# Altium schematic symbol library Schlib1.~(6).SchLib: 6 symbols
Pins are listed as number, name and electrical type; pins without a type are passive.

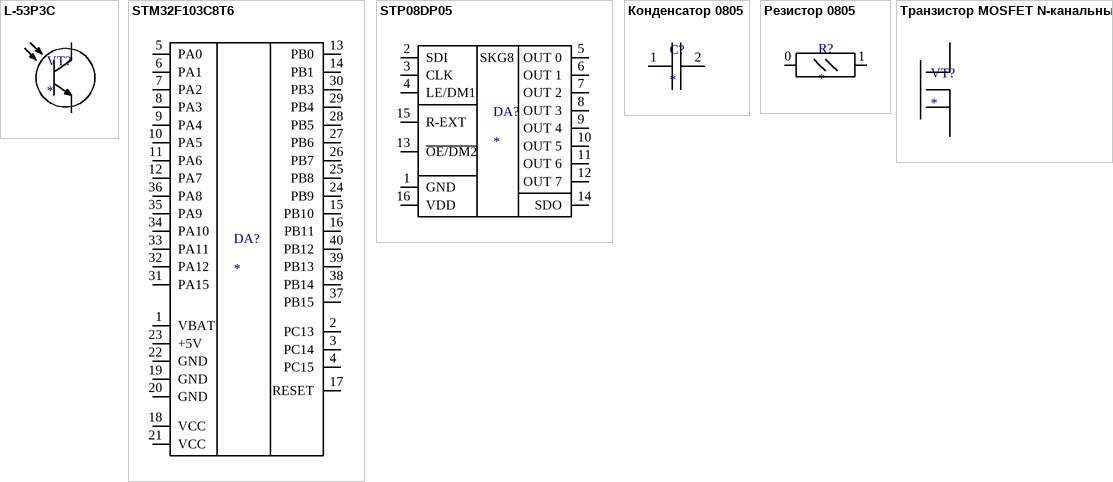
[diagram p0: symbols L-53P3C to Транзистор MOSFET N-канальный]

## L-53P3C
designator VT?

## STM32F103C8T6
designator DA?
pins: 1 VBAT, 2 PC13, 3 PC14, 4 PC15, 5 PA0, 6 PA1, 7 PA2, 8 PA3, 9 PA4, 10 PA5, 11 PA6, 12 PA7, 13 PB0, 14 PB1, 15 PB10, 16 PB11, 17 RESET, 18 VCC, 19 GND, 20 GND, 21 VCC, 22 GND, 23 +5V, 24 PB9, 25 PB8, 26 PB7, 27 PB6, 28 PB5, 29 PB4, 30 PB3, 31 PA15, 32 PA12, 33 PA11, 34 PA10, 35 PA9, 36 PA8, 37 PB15, 38 PB14, 39 PB13, 40 PB12

## STP08DP05
designator DA?
pins: 1 GND, 2 SDI, 3 CLK, 4 LE/DM1, 5 OUT 0, 6 OUT 1, 7 OUT 2, 8 OUT 3, 9 OUT 4, 10 OUT 5, 11 OUT 6, 12 OUT 7, 13 ~{OE/DM2}, 14 SDO, 15 R-EXT, 16 VDD

## Конденсатор 0805
designator С?
pins: 1, 2

## Резистор 0805
designator R?
pins: 0, 1

## Транзистор MOSFET N-канальный
designator VT?
Транзистор MOSFET N-канальный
